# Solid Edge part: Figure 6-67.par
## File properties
Author: TIET
Template: Iso Metric Part.par
Last saved by: CADCIM
Revision: 3
Application: Solid Edge
Accuracy: 0.990
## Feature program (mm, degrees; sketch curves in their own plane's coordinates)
pattern "unnamed Pattern 1"
Other named dimensions: "Pattern_3": XOffset = 45 deg
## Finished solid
Body 1: solid body, 12 faces, 20 edges, 0 vertices.
  Faces by surface: cylinder 10, plane 2
  Edges by curve: circle 20
Bounding box of the edges (mm): 106.295 x 6.758 x 106.295, from (-53.1477, -3.3791, -53.1477) to (53.1477, 3.3791, 53.1477).
Cylindrical faces by radius (mm): R3.7218 x8, R16.5187 x1, R53.1477 x1
Planar faces by outward normal: +y 1, -y 1
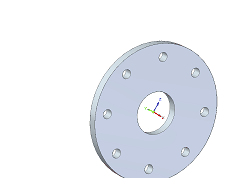
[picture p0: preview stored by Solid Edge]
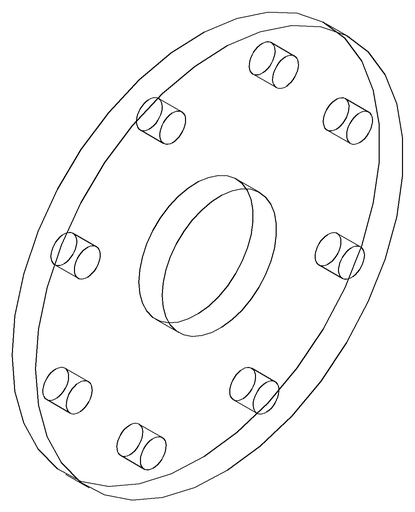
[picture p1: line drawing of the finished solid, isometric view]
